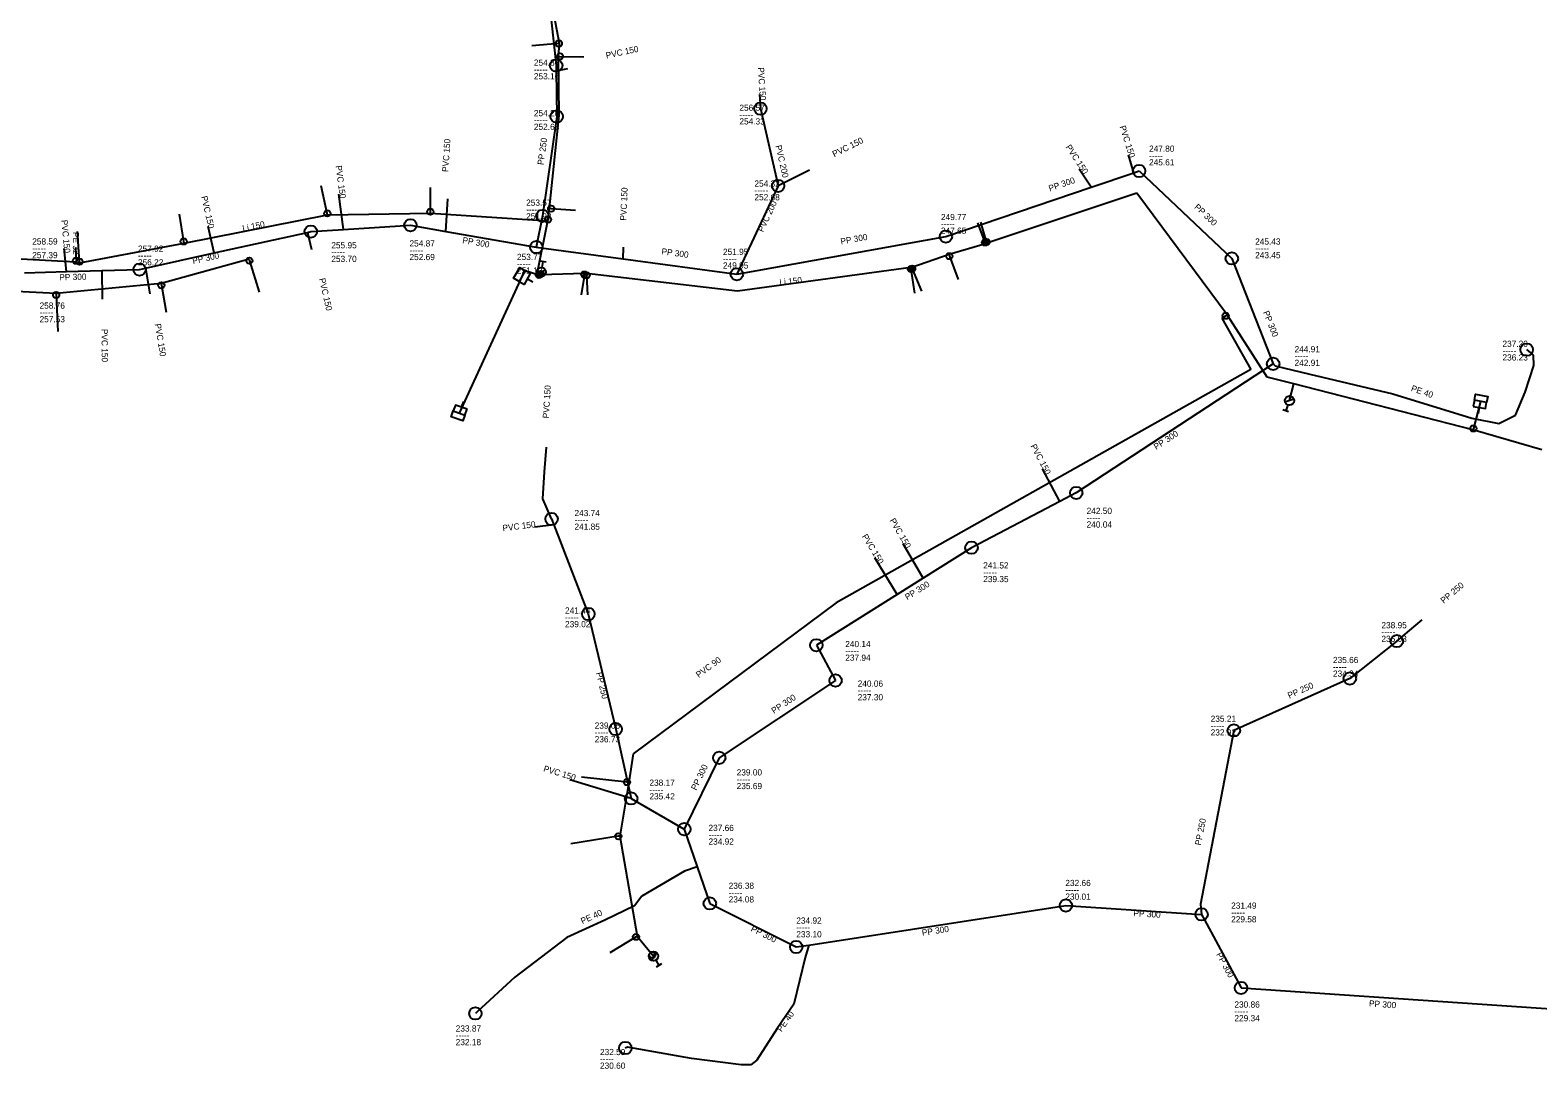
# Model space of a CAD drawing. Extents: x -770828 to -770111, y -1050344 to -1049447.
# Drawn here: x -770523.9 to -770280.9, y -1050253.9 to -1050086.5 of the extents above; entities that cross this region are included whole.
import ezdxf

# ---------------------------------------------------------------- set-up
doc = ezdxf.new("R2010")
doc.units = 0
doc.layers.add('Level 0', color=7, linetype='Continuous')

msp = doc.modelspace()

# ---------------------------------------------------------------- linework, layer by layer
at = {"layer": 'Level 0'}
for p, q in [((-770438.53, -1050088.64), (-770440.42, -1050078.8)), ((-770439.91, -1050084.82), (-770439.09, -1050092.2)), ((-770438.66, -1050088.64), (-770442.99, -1050089.02)), ((-770438.69, -1050090.72), (-770438.53, -1050088.64)), ((-770438.53, -1050088.64), (-770438.66, -1050088.64)), ((-770439.09, -1050092.2), (-770439.08, -1050093.05)), ((-770438.69, -1050090.72), (-770438.49, -1050090.72)), ((-770438.61, -1050100.23), (-770438.69, -1050090.72)), ((-770438.49, -1050090.72), (-770434.61, -1050090.81)), ((-770439.08, -1050093.05), (-770437.2, -1050092.65)), ((-770439.08, -1050093.05), (-770439.01, -1050100.4)), ((-770406.32, -1050096.84), (-770406.17, -1050099.14)), ((-770406.17, -1050099.14), (-770403.32, -1050111.59)), ((-770439.01, -1050100.4), (-770441.3, -1050116.43)), ((-770440.14, -1050115.14), (-770438.61, -1050100.23)), ((-770345.97, -1050109.47), (-770346.87, -1050106.61)), ((-770398.81, -1050109.34), (-770403.32, -1050111.59)), ((-770398.27, -1050109.07), (-770398.81, -1050109.34)), ((-770352.86, -1050111.81), (-770354.8, -1050108.88)), ((-770352.86, -1050111.81), (-770345.97, -1050109.47)), ((-770345.97, -1050109.47), (-770345.14, -1050109.19)), ((-770345.14, -1050109.19), (-770330.2, -1050123.29)), ((-770475.98, -1050116.02), (-770476.98, -1050111.56)), ((-770459.37, -1050115.77), (-770459.33, -1050111.83)), ((-770403.32, -1050111.59), (-770409.97, -1050125.83)), ((-770376.28, -1050119.76), (-770352.86, -1050111.81)), ((-770473.38, -1050118.62), (-770474.13, -1050112.95)), ((-770456.88, -1050118.92), (-770456.53, -1050113.7)), ((-770345.53, -1050112.74), (-770369.68, -1050120.85)), ((-770330.93, -1050132.4), (-770345.53, -1050112.74)), ((-770499.11, -1050120.56), (-770499.81, -1050116.13)), ((-770499.07, -1050120.8), (-770475.94, -1050116.26)), ((-770475.94, -1050116.26), (-770475.98, -1050116.02)), ((-770475.94, -1050116.26), (-770459.37, -1050116.01)), ((-770459.37, -1050116.01), (-770459.37, -1050115.77)), ((-770459.37, -1050116.01), (-770440.41, -1050117.25)), ((-770441.3, -1050116.43), (-770442.29, -1050121.46)), ((-770440.39, -1050117.01), (-770440.14, -1050115.14)), ((-770440.14, -1050115.14), (-770439.9, -1050115.26)), ((-770439.9, -1050115.26), (-770435.99, -1050115.48)), ((-770515.9, -1050123.82), (-770516.24, -1050118.95)), ((-770494.2, -1050122.4), (-770495.18, -1050118.15)), ((-770494.2, -1050122.4), (-770479.17, -1050119.08)), ((-770479.17, -1050119.08), (-770478.63, -1050118.96)), ((-770479.17, -1050119.08), (-770478.54, -1050121.82)), ((-770478.63, -1050118.96), (-770473.38, -1050118.62)), ((-770473.38, -1050118.62), (-770462.58, -1050117.93)), ((-770462.58, -1050117.93), (-770456.88, -1050118.92)), ((-770456.88, -1050118.92), (-770442.29, -1050121.46)), ((-770442.18, -1050125.77), (-770440.41, -1050117.25)), ((-770440.41, -1050117.25), (-770440.39, -1050117.01)), ((-770369.97, -1050120.72), (-770371.11, -1050117.56)), ((-770369.74, -1050120.63), (-770370.64, -1050117.45)), ((-770518.03, -1050125.41), (-770518.39, -1050121.66)), ((-770516.58, -1050121.55), (-770516.47, -1050123.67)), ((-770515.89, -1050124), (-770499.07, -1050120.8)), ((-770499.07, -1050120.8), (-770499.11, -1050120.56)), ((-770442.29, -1050121.46), (-770428.32, -1050123.35)), ((-770428.32, -1050123.35), (-770428.24, -1050121.47)), ((-770409.97, -1050125.83), (-770376.28, -1050119.76)), ((-770369.9, -1050120.91), (-770375.78, -1050122.67)), ((-770369.9, -1050120.91), (-770369.97, -1050120.72)), ((-770369.68, -1050120.85), (-770369.9, -1050120.91)), ((-770369.68, -1050120.85), (-770369.74, -1050120.63)), ((-770528.25, -1050123.18), (-770516.49, -1050123.86)), ((-770516.47, -1050123.67), (-770516.49, -1050123.86)), ((-770516.49, -1050123.86), (-770515.89, -1050124)), ((-770515.89, -1050124), (-770515.9, -1050123.82)), ((-770505.29, -1050124.87), (-770494.2, -1050122.4)), ((-770488.56, -1050123.41), (-770502.75, -1050127.35)), ((-770488.56, -1050123.41), (-770488.52, -1050123.66)), ((-770488.52, -1050123.66), (-770486.97, -1050128.7)), ((-770441.68, -1050123.67), (-770440.69, -1050123.84)), ((-770441.36, -1050124.74), (-770441.19, -1050123.76)), ((-770428.32, -1050123.35), (-770409.97, -1050125.83)), ((-770375.78, -1050122.67), (-770381.76, -1050124.74)), ((-770375.78, -1050122.67), (-770375.72, -1050122.92)), ((-770375.72, -1050122.92), (-770374.33, -1050126.66)), ((-770330.2, -1050123.29), (-770323.54, -1050140.28)), ((-770524.78, -1050125.6), (-770518.03, -1050125.41)), ((-770518.03, -1050125.41), (-770512.29, -1050125.25)), ((-770512.29, -1050125.25), (-770506.23, -1050125.08)), ((-770512.29, -1050125.25), (-770512.24, -1050129.88)), ((-770506.23, -1050125.08), (-770505.29, -1050124.87)), ((-770505.29, -1050124.87), (-770504.6, -1050129.02)), ((-770444.58, -1050126.11), (-770454.73, -1050148.21)), ((-770444.23, -1050125.25), (-770444.58, -1050126.11)), ((-770441.88, -1050125.96), (-770444.23, -1050125.25)), ((-770441.56, -1050125.92), (-770442.18, -1050125.77)), ((-770442.15, -1050125.83), (-770440.83, -1050125.13)), ((-770441.85, -1050125.85), (-770441.88, -1050125.96)), ((-770441.6, -1050125.78), (-770441.49, -1050125.48)), ((-770441.56, -1050125.92), (-770441.6, -1050125.78)), ((-770434.53, -1050125.73), (-770441.56, -1050125.92)), ((-770434.55, -1050125.88), (-770435.04, -1050129.14)), ((-770434.53, -1050125.73), (-770434.55, -1050125.88)), ((-770434.2, -1050125.72), (-770434.53, -1050125.73)), ((-770434.2, -1050125.72), (-770434.19, -1050125.99)), ((-770409.86, -1050128.59), (-770434.2, -1050125.72)), ((-770434.19, -1050125.99), (-770434.06, -1050129.14)), ((-770381.94, -1050124.76), (-770409.86, -1050128.59)), ((-770381.76, -1050124.74), (-770381.94, -1050124.76)), ((-770381.94, -1050124.76), (-770381.91, -1050125)), ((-770381.91, -1050125), (-770381.35, -1050128.88)), ((-770381.76, -1050124.74), (-770381.71, -1050124.95)), ((-770381.71, -1050124.95), (-770380.19, -1050128.54)), ((-770519.68, -1050128.92), (-770534.58, -1050128.19)), ((-770502.75, -1050127.35), (-770519.68, -1050128.92)), ((-770519.68, -1050128.92), (-770519.67, -1050129.17)), ((-770502.75, -1050127.35), (-770502.71, -1050127.61)), ((-770502.71, -1050127.61), (-770501.97, -1050131.94)), ((-770442.85, -1050127.11), (-770443.71, -1050126.61)), ((-770519.67, -1050129.17), (-770519.42, -1050135.05)), ((-770331.19, -1050132.54), (-770331.83, -1050132.89)), ((-770331.83, -1050132.89), (-770327.16, -1050141.19)), ((-770330.93, -1050132.4), (-770331.19, -1050132.54)), ((-770324.52, -1050142.42), (-770330.93, -1050132.4)), ((-770282.36, -1050138.19), (-770282.68, -1050137.99)), ((-770281.59, -1050138.87), (-770282.36, -1050138.19)), ((-770323.54, -1050140.28), (-770355.27, -1050161.08)), ((-770323.54, -1050140.28), (-770323.22, -1050140.62)), ((-770323.22, -1050140.62), (-770317.65, -1050141.95)), ((-770282.91, -1050144.86), (-770281.54, -1050140.52)), ((-770281.54, -1050140.52), (-770281.59, -1050138.87)), ((-770327.16, -1050141.19), (-770393.96, -1050178.83)), ((-770320.23, -1050143.52), (-770324.52, -1050142.42)), ((-770320.92, -1050146.21), (-770320.23, -1050143.52)), ((-770291.37, -1050150.94), (-770320.23, -1050143.52)), ((-770317.65, -1050141.95), (-770304.26, -1050145.1)), ((-770320.21, -1050145.98), (-770321.63, -1050146.44)), ((-770304.26, -1050145.1), (-770291.53, -1050149.02)), ((-770284.49, -1050148.58), (-770282.91, -1050144.86)), ((-770454.05, -1050146.33), (-770454.39, -1050147.27)), ((-770321.05, -1050148.03), (-770321.99, -1050147.68)), ((-770321.18, -1050146.91), (-770321.52, -1050147.85)), ((-770290.12, -1050146.33), (-770291.26, -1050150.7)), ((-770290.47, -1050148.3), (-770290.29, -1050147.31)), ((-770291.53, -1050149.02), (-770287.18, -1050149.92)), ((-770291.26, -1050150.7), (-770291.37, -1050150.94)), ((-770287.18, -1050149.92), (-770284.49, -1050148.58)), ((-770280.22, -1050154.16), (-770291.37, -1050150.94)), ((-770440.98, -1050157.68), (-770440.63, -1050153.71)), ((-770441.25, -1050162.05), (-770440.98, -1050157.68)), ((-770357.92, -1050162.47), (-770360.69, -1050157.23)), ((-770439.83, -1050165.29), (-770441.25, -1050162.05)), ((-770357.92, -1050162.47), (-770372.15, -1050169.92)), ((-770355.27, -1050161.08), (-770357.92, -1050162.47)), ((-770439.83, -1050165.29), (-770439.46, -1050166.25)), ((-770439.46, -1050166.25), (-770442.55, -1050166.62)), ((-770439.46, -1050166.25), (-770433.91, -1050180.6)), ((-770379.96, -1050174.83), (-770383.18, -1050169.29)), ((-770372.15, -1050169.92), (-770379.96, -1050174.83)), ((-770384.13, -1050177.45), (-770387.75, -1050171.53)), ((-770379.96, -1050174.83), (-770384.13, -1050177.45)), ((-770384.13, -1050177.45), (-770397.16, -1050185.64)), ((-770393.96, -1050178.83), (-770426.7, -1050203.15)), ((-770433.91, -1050180.6), (-770429.5, -1050199.16)), ((-770303.6, -1050184.98), (-770299.54, -1050181.56)), ((-770397.16, -1050185.64), (-770394.06, -1050191.33)), ((-770303.6, -1050184.98), (-770311.18, -1050191)), ((-770394.06, -1050191.33), (-770412.81, -1050203.79)), ((-770311.18, -1050191), (-770329.87, -1050199.37)), ((-770429.5, -1050199.16), (-770427, -1050210.34)), ((-770329.87, -1050199.37), (-770335.26, -1050227.37)), ((-770426.7, -1050203.15), (-770427.38, -1050207.73)), ((-770412.81, -1050203.79), (-770418.44, -1050215.3)), ((-770427, -1050210.34), (-770436.87, -1050207.34)), ((-770427.66, -1050207.72), (-770435, -1050206.89)), ((-770427.38, -1050207.73), (-770428.84, -1050216.44)), ((-770427.38, -1050207.73), (-770427.66, -1050207.72)), ((-770427, -1050210.34), (-770418.44, -1050215.3)), ((-770429.08, -1050216.44), (-770436.72, -1050217.65)), ((-770428.84, -1050216.44), (-770429.08, -1050216.44)), ((-770428.84, -1050216.44), (-770426.01, -1050232.54)), ((-770418.44, -1050215.3), (-770416.36, -1050221.35)), ((-770418.41, -1050222.04), (-770425.26, -1050226.08)), ((-770416.36, -1050221.35), (-770418.41, -1050222.04)), ((-770416.36, -1050221.35), (-770414.32, -1050227.27)), ((-770425.26, -1050226.08), (-770426.45, -1050227.63)), ((-770426.45, -1050227.63), (-770431.27, -1050229.98)), ((-770414.32, -1050227.27), (-770400.4, -1050234.29)), ((-770398.39, -1050233.98), (-770356.94, -1050227.6)), ((-770356.94, -1050227.6), (-770335.08, -1050229.03)), ((-770335.26, -1050227.37), (-770335.08, -1050229.03)), ((-770431.27, -1050229.98), (-770437.36, -1050232.77)), ((-770335.08, -1050229.03), (-770334.59, -1050229.93)), ((-770334.59, -1050229.93), (-770329.15, -1050240.09)), ((-770437.36, -1050232.77), (-770445.77, -1050239.17)), ((-770426.21, -1050232.66), (-770430.46, -1050235.22)), ((-770426.01, -1050232.54), (-770426.21, -1050232.66)), ((-770426.01, -1050232.54), (-770423.58, -1050235.56)), ((-770423.14, -1050235.07), (-770423.7, -1050236.46)), ((-770423.58, -1050235.56), (-770423.42, -1050235.76)), ((-770400.4, -1050234.29), (-770398.39, -1050233.98)), ((-770398.39, -1050233.98), (-770398.94, -1050235.98)), ((-770423.05, -1050236.41), (-770422.55, -1050237.28)), ((-770422.11, -1050237.03), (-770422.98, -1050237.53)), ((-770398.94, -1050235.98), (-770400.79, -1050243.49)), ((-770445.77, -1050239.17), (-770451.81, -1050244.73)), ((-770329.15, -1050240.09), (-770328.72, -1050240.89)), ((-770328.72, -1050240.89), (-770277.18, -1050244.39)), ((-770451.81, -1050244.73), (-770452.11, -1050245)), ((-770400.79, -1050243.49), (-770403.49, -1050247.41)), ((-770403.49, -1050247.41), (-770406.75, -1050252.53)), ((-770427.59, -1050250.44), (-770427.95, -1050250.58)), ((-770417.3, -1050252.29), (-770427.59, -1050250.44)), ((-770409.29, -1050253.28), (-770417.3, -1050252.29)), ((-770406.75, -1050252.53), (-770407.71, -1050253.27)), ((-770407.71, -1050253.27), (-770409.29, -1050253.28))]:
    msp.add_line(p, q, dxfattribs=at)
for points in [[(-770445.08, -1050126.98), (-770445.95, -1050126.48), (-770444.95, -1050124.74), (-770444.08, -1050125.24)], [(-770291.1, -1050146.16), (-770290.93, -1050145.17), (-770288.96, -1050145.52), (-770289.14, -1050146.5)], [(-770453.79, -1050148.55), (-770454.13, -1050149.49), (-770456.01, -1050148.81), (-770455.67, -1050147.87)]]:
    msp.add_lwpolyline(points, dxfattribs=at)
for points in [[(-770444.21, -1050127.48), (-770443.21, -1050125.74), (-770444.08, -1050125.24), (-770445.08, -1050126.98)], [(-770453.45, -1050147.61), (-770455.33, -1050146.93), (-770455.67, -1050147.87), (-770453.79, -1050148.55)], [(-770291.28, -1050147.14), (-770289.31, -1050147.49), (-770289.14, -1050146.5), (-770291.1, -1050146.16)]]:
    msp.add_lwpolyline(points, close=True, dxfattribs=at)
for centre, radius in [((-770438.66, -1050088.64), 0.5), ((-770439.09, -1050092.2), 1), ((-770438.49, -1050090.72), 0.5), ((-770439.01, -1050100.4), 1), ((-770406.17, -1050099.14), 1), ((-770345.14, -1050109.19), 1), ((-770403.32, -1050111.59), 1), ((-770475.98, -1050116.02), 0.5), ((-770459.37, -1050115.77), 0.5), ((-770441.3, -1050116.43), 1), ((-770440.39, -1050117.01), 0.5), ((-770439.9, -1050115.26), 0.5), ((-770478.63, -1050118.96), 1), ((-770462.58, -1050117.93), 1), ((-770376.28, -1050119.76), 1), ((-770499.11, -1050120.56), 0.5), ((-770442.29, -1050121.46), 1), ((-770369.97, -1050120.72), 0.5), ((-770369.74, -1050120.63), 0.5), ((-770516.47, -1050123.67), 0.5), ((-770515.9, -1050123.82), 0.5), ((-770506.23, -1050125.08), 1), ((-770488.52, -1050123.66), 0.5), ((-770375.72, -1050122.92), 0.5), ((-770330.2, -1050123.29), 1), ((-770441.88, -1050125.96), 0.5), ((-770441.49, -1050125.48), 0.75), ((-770441.6, -1050125.78), 0.5), ((-770434.55, -1050125.88), 0.5), ((-770434.19, -1050125.99), 0.5), ((-770409.97, -1050125.83), 1), ((-770381.91, -1050125), 0.5), ((-770381.71, -1050124.95), 0.5), ((-770519.67, -1050129.17), 0.5), ((-770502.71, -1050127.61), 0.5), ((-770331.19, -1050132.54), 0.5), ((-770282.68, -1050137.99), 1), ((-770323.54, -1050140.28), 1), ((-770320.92, -1050146.21), 0.75), ((-770291.26, -1050150.7), 0.5), ((-770355.27, -1050161.08), 1), ((-770439.83, -1050165.29), 1), ((-770372.15, -1050169.92), 1), ((-770433.91, -1050180.6), 1), ((-770397.16, -1050185.64), 1), ((-770303.6, -1050184.98), 1), ((-770394.06, -1050191.33), 1), ((-770311.18, -1050191), 1), ((-770429.5, -1050199.16), 1), ((-770329.87, -1050199.37), 1), ((-770412.81, -1050203.79), 1), ((-770427.66, -1050207.72), 0.5), ((-770427, -1050210.34), 1), ((-770429.08, -1050216.44), 0.5), ((-770418.44, -1050215.3), 1), ((-770414.32, -1050227.27), 1), ((-770356.94, -1050227.6), 1), ((-770335.08, -1050229.03), 1), ((-770426.21, -1050232.66), 0.5), ((-770400.4, -1050234.29), 1), ((-770423.42, -1050235.76), 0.75), ((-770423.58, -1050235.56), 0.5), ((-770328.72, -1050240.89), 1), ((-770452.11, -1050245), 1), ((-770427.95, -1050250.58), 1)]:
    msp.add_circle(centre, radius, dxfattribs=at)

# ---------------------------------------------------------------- texts
for s, rotation, p in [('PVC 150', 12.011, (-770430.98, -1050091.07)), ('PVC 150', 273.731, (-770406.59, -1050092.51)), ('PVC 150', 287.468, (-770348.3, -1050102.04)), ('PVC 150', 86.164, (-770456.48, -1050109.38)), ('PP 250', 81.87, (-770441.14, -1050108.27)), ('PVC 150', 26.514, (-770394.27, -1050106.98)), ('PVC 200', 282.894, (-770403.77, -1050105.14)), ('PVC 150', 303.509, (-770357.04, -1050105.35)), ('PVC 150', 277.535, (-770474.64, -1050108.37)), ('PVC 150', 87.563, (-770427.79, -1050117.21)), ('PP 300', 18.759, (-770359.53, -1050112.5)), ('PVC 150', 282.985, (-770496.32, -1050113.33)), ('PVC 200', 64.968, (-770405.74, -1050119.13)), ('PP 300', 316.657, (-770336.33, -1050115.11)), ('PVC 150', 275.484, (-770518.86, -1050117.12)), ('PE 32', 270, (-770516.98, -1050119.03)), ('Li 150', 11.105, (-770489.56, -1050118.93)), ('PP 300', 350.147, (-770454.26, -1050120.81)), ('PP 300', 352.295, (-770422.17, -1050122.62)), ('PP 300', 10.214, (-770393.17, -1050121.05)), ('PP 300', 12.556, (-770497.6, -1050124.2)), ('PP 300', 1.612, (-770519.16, -1050126.84)), ('PVC 150', 282.949, (-770477.32, -1050126.58)), ('Li 150', 6.34, (-770403.05, -1050127.66)), ('PVC 150', 279.44, (-770503.79, -1050133.88)), ('PP 300', 291.405, (-770325.18, -1050131.96)), ('PVC 150', 270.619, (-770512.38, -1050134.65)), ('PVC 150', 86.464, (-770440.27, -1050149.09)), ('PE 40', 340.76, (-770301.4, -1050144.62)), ('PVC 150', 297.862, (-770362.68, -1050153.53)), ('PP 300', 33.246, (-770342.38, -1050154.18)), ('PVC 150', 300.166, (-770385.39, -1050165.52)), ('PVC 150', 6.828, (-770447.68, -1050167.26)), ('PVC 150', 301.445, (-770389.86, -1050168.1)), ('PP 300', 32.141, (-770382.5, -1050178.41)), ('PP 250', 40.11, (-770296.05, -1050178.97)), ('PVC 90', 36.261, (-770416.11, -1050190.94)), ('PP 250', 283.366, (-770432.68, -1050190.11)), ('PP 250', 24.124, (-770320.93, -1050194.27)), ('PP 300', 33.605, (-770403.99, -1050196.73)), ('PVC 150', 343.093, (-770441.23, -1050205.95)), ('PP 300', 63.935, (-770416.52, -1050209.11)), ('PP 250', 79.104, (-770335.18, -1050217.97)), ('PE 40', 24.614, (-770434.85, -1050230.63)), ('PP 300', 356.257, (-770346.08, -1050229.31)), ('PP 300', 333.238, (-770407.81, -1050231.67)), ('PP 300', 8.768, (-770380.07, -1050232.5)), ('PP 300', 298.166, (-770332.75, -1050235.48)), ('PP 300', 356.115, (-770308.12, -1050243.87)), ('PE 40', 54.596, (-770402.78, -1050248.05))]:
    msp.add_text(s, height=1, rotation=rotation, dxfattribs=at).set_placement(p)
for s, p in [('254.87', (-770442.68, -1050092.22)), ('-----', (-770442.68, -1050093.32)), ('253.16', (-770442.68, -1050094.42)), ('254.20', (-770442.68, -1050100.36)), ('256.57', (-770409.56, -1050099.49)), ('-----', (-770442.68, -1050101.46)), ('252.63', (-770442.68, -1050102.56)), ('-----', (-770409.56, -1050100.59)), ('254.33', (-770409.56, -1050101.69)), ('-----', (-770343.54, -1050107.19)), ('247.80', (-770343.54, -1050106.09)), ('245.61', (-770343.54, -1050108.29)), ('254.32', (-770407.14, -1050111.72)), ('253.57', (-770443.93, -1050114.79)), ('-----', (-770407.14, -1050112.82)), ('252.68', (-770407.14, -1050113.92)), ('-----', (-770443.93, -1050115.89)), ('251.93', (-770443.93, -1050116.99)), ('249.77', (-770377.08, -1050117.11)), ('-----', (-770377.08, -1050118.21)), ('247.65', (-770377.08, -1050119.31)), ('258.59', (-770523.53, -1050121.05)), ('257.92', (-770506.49, -1050122.21)), ('255.95', (-770475.33, -1050121.66)), ('254.87', (-770462.73, -1050121.36)), ('245.43', (-770326.44, -1050121.06)), ('-----', (-770523.53, -1050122.15)), ('257.39', (-770523.53, -1050123.25)), ('-----', (-770506.49, -1050123.31)), ('256.22', (-770506.49, -1050124.41)), ('-----', (-770475.33, -1050122.76)), ('253.70', (-770475.33, -1050123.86)), ('-----', (-770462.73, -1050122.46)), ('252.69', (-770462.73, -1050123.56)), ('253.77', (-770445.41, -1050123.54)), ('-----', (-770412.21, -1050123.82)), ('251.95', (-770412.21, -1050122.72)), ('249.95', (-770412.21, -1050124.92)), ('-----', (-770326.44, -1050122.16)), ('243.45', (-770326.44, -1050123.26)), ('-----', (-770445.41, -1050124.64)), ('251.10', (-770445.41, -1050125.74)), ('258.76', (-770522.35, -1050131.39)), ('-----', (-770522.35, -1050132.49)), ('257.53', (-770522.35, -1050133.59)), ('244.91', (-770320.09, -1050138.42)), ('-----', (-770286.58, -1050138.64)), ('237.20', (-770286.58, -1050137.54)), ('-----', (-770320.09, -1050139.52)), ('242.91', (-770320.09, -1050140.62)), ('236.23', (-770286.58, -1050139.74)), ('243.74', (-770436.14, -1050164.83)), ('-----', (-770353.6, -1050165.58)), ('242.50', (-770353.6, -1050164.48)), ('-----', (-770436.14, -1050165.93)), ('241.85', (-770436.14, -1050167.03)), ('240.04', (-770353.6, -1050166.68)), ('241.52', (-770370.27, -1050173.27)), ('-----', (-770370.27, -1050174.37)), ('239.35', (-770370.27, -1050175.47)), ('241.44', (-770437.66, -1050180.54)), ('-----', (-770437.66, -1050181.64)), ('239.02', (-770437.66, -1050182.74)), ('238.95', (-770306.09, -1050182.91)), ('-----', (-770306.09, -1050184.01)), ('236.03', (-770306.09, -1050185.11)), ('-----', (-770392.5, -1050187.05)), ('240.14', (-770392.5, -1050185.95)), ('237.94', (-770392.5, -1050188.15)), ('-----', (-770313.9, -1050189.62)), ('235.66', (-770313.9, -1050188.52)), ('234.34', (-770313.9, -1050190.72)), ('240.06', (-770390.5, -1050192.33)), ('-----', (-770390.5, -1050193.43)), ('237.30', (-770390.5, -1050194.53)), ('235.21', (-770333.61, -1050197.99)), ('239.06', (-770432.88, -1050199.1)), ('-----', (-770333.61, -1050199.09)), ('232.92', (-770333.61, -1050200.19)), ('-----', (-770432.88, -1050200.2)), ('236.73', (-770432.88, -1050201.3)), ('239.00', (-770410, -1050206.64)), ('-----', (-770424.06, -1050209.4)), ('238.17', (-770424.06, -1050208.3)), ('-----', (-770410, -1050207.74)), ('235.69', (-770410, -1050208.84)), ('235.42', (-770424.06, -1050210.5)), ('-----', (-770414.54, -1050216.69)), ('237.66', (-770414.54, -1050215.59)), ('234.92', (-770414.54, -1050217.79)), ('232.66', (-770357.03, -1050224.47)), ('-----', (-770411.29, -1050226.01)), ('236.38', (-770411.29, -1050224.91)), ('234.08', (-770411.29, -1050227.11)), ('-----', (-770357.03, -1050225.57)), ('230.01', (-770357.03, -1050226.67)), ('231.49', (-770330.31, -1050228.12)), ('234.92', (-770400.39, -1050230.53)), ('-----', (-770330.31, -1050229.22)), ('229.58', (-770330.31, -1050230.32)), ('-----', (-770400.39, -1050231.63)), ('233.10', (-770400.39, -1050232.73)), ('230.86', (-770329.78, -1050244.06)), ('-----', (-770329.78, -1050245.16)), ('229.34', (-770329.78, -1050246.26)), ('233.87', (-770455.28, -1050247.92)), ('-----', (-770455.28, -1050249.02)), ('232.18', (-770455.28, -1050250.12)), ('-----', (-770432.03, -1050252.82)), ('232.59', (-770432.03, -1050251.72)), ('230.60', (-770432.03, -1050253.92))]:
    msp.add_text(s, height=1, dxfattribs=at).set_placement(p)

doc.saveas('drawing.dxf')
